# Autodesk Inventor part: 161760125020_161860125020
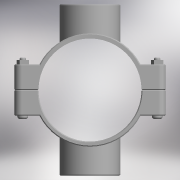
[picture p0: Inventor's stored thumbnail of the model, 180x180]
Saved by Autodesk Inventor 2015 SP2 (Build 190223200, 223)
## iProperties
Created: 2017-05
Part Number: 161760125020_161860125020
Material: Generic
Description: PLASSON DOUBLE SADDLE 125-2"
Document SubType Name: Modeling
Designer: KIM
Density: 1 g/cm^3
Appearance: Default
Author: KIM
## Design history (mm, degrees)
derived "16176.ipt"
feature "Solid1::16176.ipt"
feature "Solid2::16176.ipt"
tag "TaggingFeature1"
body "Solid1"
body "Solid2"
other parameters: "d0" = 137.5, "d1" = 184, "d2" = 62.5, "d3" = 125, "d4" = 124, "d5" = 0, "d6" = 9.2, "d7" = 184, "d8" = 0.1, "d10" = 0, "d11" = 1.25, "d20" = 1.25, "d23" = 1.25, "d36" = 13, "d37" = 10.4, "d38" = 70.5, "d39" = 0, "d40" = 3, "d41" = 5, "d42" = 0, "d43" = 8, "d44" = 3, "d45" = 0, "d46" = 1.25, "d52" = 56.656, "d54" = 0, "d57" = 0, "d58" = 135, "d60" = 0, "d62" = 13, "d63" = 10.4, "d66" = 103.2, "d67" = 208, "d68" = 73.6528, "d69" = 56.656, "d71" = 0, "d74" = 0, "d75" = 1.25, "d_" = 125, "G_" = 56.656, "A_" = 104, "L_" = 184, "L_1" = 124
